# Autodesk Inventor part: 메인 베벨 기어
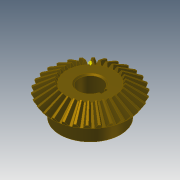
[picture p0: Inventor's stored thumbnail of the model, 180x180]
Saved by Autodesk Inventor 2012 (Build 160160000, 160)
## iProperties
Created: 2014-10
Part Number: 메인 베벨 기어
Material: Steel, Mild
Document SubType Name: Modeling
Designer: KYOUNG IL JANG
Categories: <?xml version="1.0" encoding="UTF-16"?> <MemberInstance><Categories><FamilyTemplate><FamilyTemplateParameter ValueType="xs:double" Id="1" ObjectReferenceKey="da
Mass: 269.583 g
Surface Area: 108.837 cm^2
Volume: 34.2981 cm^3
Density: 7.86 g/cm^3
CustomPartVersion: 1
Company: 한국ATC센터
Author: KYOUNG IL JANG
Revision Number: 1
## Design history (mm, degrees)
node "맨 위 점"
node "메쉬 평면2"
sketch "톱니 본체 스케치"
  geometry: L1 (0, 0)-(28.669, -21.997); L2 (28.669, -21.997)-(31.109, -18.336); L3 (31.109, -18.336)-(0, 0); L4 (30, -20)-(0, 0); L5 (17.219, -13.212)-(18.685, -11.013); L6 (28.669, -21.997)-(17.219, -13.212); L7 (31.109, -18.336)-(18.685, -11.013); L8 (0, -39.387)-(0, 6.564) reference; L9 (0, -20)-(31.109, -20)
  constraints: 16 end point, 4 point on line, 3 perpendicular, 2 collinear, 1 horizontal alignment, 1 vertical alignment
  dimensions: "d0" = 60 diameter of L4.start L8 (= da_de); "d1" = 57.33744 diameter of L1.end L8 (= da_dfe); "d2" = 62.2188 diameter of L2.end L8 (= da_dae); "d3" = 14.4 distance between parallel lines of L2 L5 (= da_b); "d4" = 18.3359 vertical distance of L2.end L1.start (= da_ve)
revolve "톱니 본체" sketch "톱니 본체 스케치" stored, may be unused: angle "d5" = 90 deg
node "시작점"
node "톱니 평면"
sketch "시작 스케치"
  geometry: L1 (0, -23.505)-(0, 10.645) reference; L2 (-0.709, -2.928)-(0.709, -2.928); A1 r 19.188 centre (-19.457, -7.014) between (-0.709, -2.928) and (-3.232, 3.229); A2 r 19.188 centre (19.457, -7.014) between (3.232, 3.229) and (0.709, -2.928); A3 r 57.403 centre (0, -54.083) between (3.232, 3.229) and (-3.232, 3.229); 1 further point
  constraints: 6 point on circle, 3 centre point, 3 symmetric about line, 2 end point, 1 coincident, 1 perpendicular, 1 other
  dimensions: "d7" = 19.18795 radius of A1 (= fd_rr); "d8" = 19.45712 horizontal distance of point (0, -54.083) A1.centre (= fd_x); "d9" = 47.06905 vertical distance of point (0, -54.083) A1.centre (= fd_y); "d57" = 57.40327 radius of A3 (= 0.5 x fd_dva + 0.3 x da_he); "d58" = 51.15527 distance from line of A3.centre L2 (= 0.5 x fd_dva - 1.12 x da_he)
node "끝점"
  node "끝 평면"
sketch "3D 스케치 오른쪽"
  node "Helical Curve Right" dims "d65" = 229.90621 (computed from da_dm, da_delta, da_beta), "d66" = 31.5, "d67" = 60 (= da_de), "d68" = -9.82794 (= -da_delta), "d69" = 8.10972 (computed from fd_loft, da_delta)
node "끝 평면 오른쪽"
sketch "끝 스케치 오른쪽"
  geometry: L1 (0, -41.54)-(0, 13.178) reference; L2 (-0.422, -1.69)-(0.422, -1.69); A1 r 11.427 centre (-11.587, -4.123) between (-0.422, -1.69) and (-1.925, 1.977); A2 r 11.427 centre (11.587, -4.123) between (1.925, 1.977) and (0.422, -1.69); A3 r 34.184 centre (0, -32.153) between (1.925, 1.977) and (-1.925, 1.977); 1 further point
  constraints: 6 point on circle, 3 centre point, 3 symmetric about line, 2 end point, 1 coincident, 1 perpendicular, 1 other
  dimensions: "d70" = 11.58699 horizontal distance of A3.centre A1.centre (computed from fd_x, fd_ratio); "d71" = 28.03028 vertical distance of point (0, -32.153) A1.centre (computed from fd_y, fd_ratio); "d72" = 11.4267 radius of A1 (computed from fd_rr, fd_ratio); "d73" = 30.46369 distance from line of point (0, -32.153) L2 (computed from d58, fd_ratio); "d74" = 34.18446 radius of A3 (computed from d57, fd_ratio)
feature "로프트 오른쪽" sketch "끝 스케치 오른쪽" dims "d75" = 0, "d77" = 0, "d79" = 0, "d80" = 90 deg, "d85" = 20, "d92" = 90 deg, "d93" = 90 deg, "da_teethtype" = 0 [user parameter]
sketch "3D 스케치 왼쪽"
  node "Helical Curve Left" dims "d26" = 229.90621 (computed from da_dm, da_delta, da_beta), "d27" = 8.10972 (computed from fd_loft, da_delta), "d28" = 60 (= da_de), "d29" = -9.82794 (= -da_delta)
node "끝 평면 왼쪽"
sketch "끝 스케치 왼쪽" dims "d56" = 10.3728 (derived)
  geometry: L1 (0, -43.753)-(0, 15.405) reference; L2 (-0.422, -1.678)-(0.422, -1.678); A1 r 11.427 centre (-11.587, -4.111) between (-0.422, -1.678) and (-1.925, 1.988); A2 r 11.427 centre (11.587, -4.111) between (1.925, 1.988) and (0.422, -1.678); A3 r 34.184 centre (0, -32.142) between (1.925, 1.988) and (-1.925, 1.988); 2 further points; 1 other entity
  constraints: 6 point on circle, 3 centre point, 3 symmetric about line, 2 end point, 1 coincident, 2 other
  dimensions: "d30" = 11.4267 radius of A1 (computed from fd_rr, fd_ratio); "d31" = 11.58699 horizontal distance of point (0, -32.142) A1.centre (computed from fd_x, fd_ratio); "d32" = 28.03028 vertical distance of A1.centre point (0, -32.142) (computed from fd_y, fd_ratio); "d61" = 34.18446 radius of A3 (computed from d57, fd_ratio); "d62" = 30.46369 distance from line of point (0, -32.142) L2 (computed from d58, fd_ratio)
feature "로프트 왼쪽" sketch "끝 스케치 왼쪽" dims "d35" = 0, "d37" = 0, "d39" = 0, "d40" = 90 deg, "d84" = 10, "d90" = 90 deg, "d91" = 90 deg, "da_teethtype" = 0 [user parameter]
sketch "본체 스케치"
  geometry: L1 (0, -35.038)-(0, -19.531) reference; L2 (28.669, -21.997)-(17.219, -13.212) reference; L3 (17.219, -13.212)-(0, -13.212); L4 (28.669, -21.997)-(0, -21.997)
  constraints: 4 end point, 2 perpendicular, 2 point on line
revolve "본체 고정" sketch "본체 스케치" stored, may be unused: angle "d46" = 90 deg
sketch "Sketch6"
  geometry: L1 (30, -20)-(0, 0) reference; L2 (0, -37.8)-(0, 6.3) reference
feature "피치 지름" sketch "Sketch6" dims angle "d47" = 90 deg
sketch "스케치8"
  geometry: C1 r 22.5 at (0, 0); 1 further point
  constraints: 1 centre point, 1 coincident
  dimensions: "d94" = 45 diameter of C1
extrude "돌출1" join sketch "스케치8" distance "d95" = 13; taper "d96" = 0 deg
sketch "스케치9"
  geometry: 1 further point
hole "구멍1" sketch "스케치9" at (0, 0) diameter "d97" = 17; stored, may be unused: countersink angle "d101" = 90 deg, drill point angle "d103" = 118 deg; dims "d98" = 6, "d99" = 4, "d100" = 2, "d102" = 8
sketch "스케치10"
  geometry: L1 (8.124, 2.5)-(10.8, 2.5); L2 (10.8, 2.5)-(10.8, -2.5); L3 (10.8, -2.5)-(8.124, -2.5); A1 r 8.5 centre (0, 0) between (8.124, 2.5) and (8.124, -2.5) reference; 1 further point
  constraints: 6 end point, 2 parallel, 2 point on circle, 1 horizontal, 1 perpendicular
  dimensions: "d104" = 5 distance of L1.end L2.end; "d112" = 19.3 dimension on A1 L2
extrude "돌출2" cut sketch "스케치10" stored distance "d106" = 10; taper "d107" = 0 deg
chamfer "모따기1" distance "d108" = 1; stored, may be unused: second distance "d109" = 2, angle "d110" = 45 deg
fillet "모깎기1" dims "d111" = 2
body "Solid1"
feature "로프트" dims "d17" = 0, "d18" = 90 deg, "d19" = 0, "d20" = 90 deg, "d89" = 0, "da_teethtype" = 0 [user parameter]
pattern_circular "원형 패턴" dims angle "d22" = 360 deg, "d88" = 0, "da_teethtype" = 0 [user parameter]
pattern_circular "원형 패턴 오른쪽" dims angle "d82" = 360 deg, "da_teethtype" = 0 [user parameter]
pattern_circular "원형 패턴 왼쪽" dims angle "d42" = 360 deg, "da_teethtype" = 0 [user parameter]
sketch "끝 스케치"
  geometry: L1 (0, -15.359)-(0, 6.983) reference; L2 (-0.422, -1.69)-(0.422, -1.69); A1 r 11.427 centre (-11.587, -4.123) between (-0.422, -1.69) and (-1.925, 1.977); A2 r 11.427 centre (11.587, -4.123) between (1.925, 1.977) and (0.422, -1.69); A3 r 34.184 centre (0, -32.153) between (1.925, 1.977) and (-1.925, 1.977); 1 further point
  constraints: 6 point on circle, 3 centre point, 3 symmetric about line, 2 end point, 1 coincident, 1 other
  dimensions: "d12" = 11.4267 radius of A1 (computed from fd_rr, fd_ratio); "d15" = 11.58699 horizontal distance of A1.centre point (0, -32.153) (computed from fd_x, fd_ratio); "d16" = 28.03028 vertical distance of A1.centre point (0, -32.153) (computed from fd_y, fd_ratio); "d59" = 34.18446 radius of A3 (computed from d57, fd_ratio); "d60" = 30.46369 distance from line of A3.centre L2 (computed from d58, fd_ratio)
body "Srf1"
other parameters: "da_b" = 14.4 [user parameter; used in 2 equation terms], "da_de" = 60 [user parameter; used in 4 equation terms], "da_dae" = 62.2188 [user parameter; used in 2 equation terms], "da_dfe" = 57.33744 [user parameter; used in 1 equation term], "da_le" = 36.05551 [user parameter; used in 1 equation term], "da_omega" = 90 deg [user parameter; used in 1 equation term], "da_beta" = 0 [user parameter; used in 2 equation terms], "da_delta" = 9.82794 [user parameter; used in 8 equation terms], "da_alpha" = 20 deg [user parameter; used in 2 equation terms], "da_he" = 4.4 [user parameter; used in 4 equation terms], "da_ve" = 18.3359 [user parameter; used in 1 equation term], "fd_dv" = 108.16654 (computed from da_de, da_delta) [user parameter; used in 1 equation term], "fd_dva" = 112.16654 (computed from da_dae, da_delta) [user parameter; used in 3 equation terms], "fd_dvb" = 101.6433 (computed from fd_dv, da_alpha) [user parameter; used in 2 equation terms], "da_zv" = 540.83269 [user parameter; used in 1 equation term], "fd_loft" = 14.62 (= da_b + 0.05 x da_he) [user parameter; used in 4 equation terms], "fd_ratio" = 5.95514 (computed from da_le, fd_loft) [user parameter; used in 15 equation terms], "fd_rr" = 19.18795 (computed from fd_dd, fd_dvb) [user parameter; used in 6 equation terms], "fd_angle" = 0.29367 (computed from da_zv) [user parameter; used in 4 equation terms], "fd_x1" = 1.58802 (computed from da_dvw, fd_angle) [user parameter; used in 1 equation term], "fd_y1" = 54.05995 (computed from da_dvw, fd_angle) [user parameter; used in 1 equation term], "fd_x2" = 17.8691 (computed from fd_rr, fd_angle2, fd_angle) [user parameter; used in 1 equation term], "fd_y2" = 6.9909 (computed from fd_rr, fd_angle2, fd_angle) [user parameter; used in 1 equation term], "fd_x" = 19.45712 (= fd_x1 + fd_x2) [user parameter; used in 4 equation terms], "fd_y" = 47.06905 (= fd_y1 - fd_y2) [user parameter; used in 4 equation terms], "fd_angle2" = 3.43555 (computed from fd_dvb, fd_dd, da_alpha) [user parameter; used in 2 equation terms], "fd_dd" = 108.64654 (= fd_dva - 0.8 x da_he) [user parameter; used in 2 equation terms], "da_dvw" = 108.16654 [user parameter; used in 2 equation terms], "d11" = 14.62 (= fd_loft), "da_dm" = 48.01848 [user parameter; used in 2 equation terms], "da_x" = 0 [user parameter], "da_m" = 2 [user parameter], "d48" = 0, "d49" = 0, "d50" = 90 deg (= da_omega), "d51" = 6 deg (computed from da_z), "d52" = 0, "d53" = 0, "d54" = 0
